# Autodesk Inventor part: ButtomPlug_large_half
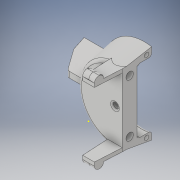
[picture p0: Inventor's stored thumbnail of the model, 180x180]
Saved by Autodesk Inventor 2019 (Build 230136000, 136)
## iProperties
Created: 2021-01
Part Number: ButtomPlug_large_half
Material: Generic
Document SubType Name: Modeling
Designer: Johnny Rex Kancaie
Density: 1 g/cm^3
Appearance: Default
Created: 2021-02
Part Number: ButtomPlug_3DPrint
Author: Johnny Rex Kancaie
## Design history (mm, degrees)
sketch "Sketch1"
  geometry: C1 r 28 at (0, 0); 1 further point
  constraints: 1 centre point, 1 coincident
  dimensions: "d0" = 56 diameter of C1
workplane "Work Plane1"
sketch "Sketch2"
  geometry: C1 r 24.5 at (0, 0); 1 further point
  constraints: 1 centre point, 1 coincident
  dimensions: "d2" = 49 diameter of C1
loft "Loft1" sketch "Sketch2" dims "d3" = 0, "d4" = 90 deg, "d5" = 0, "d6" = 90 deg
workplane "Work Plane2"
workplane "Work Plane3"
sketch "Sketch3"
  geometry: L1 (28, 0)-(-28, 0) reference; L2 (-24.5, 20)-(24.5, 20) reference; L3 (-5, 11)-(5, 11); L4 (5, 29)-(-5, 11); L5 (-5, 29)-(5, 11); L6 (-24.5, 20)-(24.5, 20) reference; L7 (5, 20)-(-5, 20); L8 (-4, 38)-(4, 38); L9 (0, 38)-(-4, 38); L10 (-4, 38)-(-5, 20); L11 (0, 38)-(4, 38); L12 (4, 38)-(5, 20); 2 further points
  constraints: 18 end point, 4 midpoint, 1 horizontal, 1 parallel, 1 point on line
  dimensions: "d9" = 10 distance of L3.end L3.start; "d13" = 4 distance of L8.start L9.start
extrude "Extrusion1" join sketch "Sketch3" distance "d15" = 2.5; taper "d16" = 0 deg
sketch "Sketch4"
  geometry: L1 (0, 0.516)-(0, 0) reference; L2 (5, 0)-(0, 0) reference; L3 (10, 0)-(5, 0) reference; L4 (10, 0.516)-(10, 0) reference; L5 (0, 0)-(0, 0.516); L6 (5, 0)-(0, 0) reference; L7 (0, 0)-(5, 0); L8 (0, 2.5)-(0, 0.516) reference; A1 r 24.5 centre (5, 24.5) between (0, 0.516) and (5, 0) reference; A2 r 24.5 centre (5, 24.5) between (5, 0) and (10, 0.516) reference; A3 r 24.5 centre (5, 24.5) between (5, 0) and (10, 0.516) reference; A4 r 24.5 centre (5, 24.5) between (0, 0.516) and (5, 0) reference; A5 r 24.5 centre (5, 24.5) between (0, 0.516) and (5, 0); 1 further point
  constraints: 4 end point, 2 point on circle, 1 centre point, 1 collinear, 1 tangent
extrude "Extrusion2" join sketch "Sketch4" distance "d17" = 4; taper "d18" = 0 deg
sketch "Sketch5"
  geometry: L1 (5, 0)-(0, 0) reference; L2 (5, 0.516)-(5, 0) reference; L3 (5, 0.516)-(5, 0) reference; L4 (5, 0.516)-(5, 0); L5 (5, 0)-(0, 0); A1 r 24.5 centre (0, 24.5) between (0, 0) and (5, 0.516) reference; A2 r 24.5 centre (0, 24.5) between (5, 0.516) and (-5, 0.516) reference; A3 r 24.5 centre (0, 24.5) between (0, 0) and (5, 0.516) reference; A4 r 24.5 centre (0, 24.5) between (0, 0) and (5, 0.516); 1 further point
  constraints: 4 end point, 2 point on circle, 1 centre point, 1 collinear, 1 concentric
extrude "Extrusion3" join sketch "Sketch5" distance "d19" = 4; taper "d20" = 0 deg
sketch "Sketch6"
  geometry: L1 (5, 20)-(5, 11); L2 (5, 11)-(-5, 11); L3 (-5, 11)-(-5, 20); L4 (-5, 29)-(5, 11); L5 (5, 29)-(-5, 11); L6 (4, 38)-(-4, 38); L7 (0, 38)-(-4, 38); L8 (-4, 38)-(-5, 20); L9 (0, 38)-(4, 38); L10 (4, 38)-(5, 20); 3 further points
  constraints: 20 end point, 3 midpoint, 1 parallel, 1 point on line
  dimensions: "d21" = 10 distance of L1.end L2.end; "d24" = 4 distance of L6.end L7.start; "d25" = 4 distance of L6.start L7.start
extrude "Extrusion4" join sketch "Sketch6" distance "d26" = 2.5; taper "d27" = 0 deg
sketch "Sketch7"
  geometry: L1 (-18.028, 0)-(0, 0) reference; L2 (0, 0)-(0, 2.5) reference; L3 (-18.028, 2.5)-(0, 2.5) reference; L4 (-18.028, 1.984)-(-18.028, 2.5) reference; L5 (-18.028, 0)-(-18.028, 1.984) reference; L6 (0, 2.5)-(0.444, 2.5) reference; L7 (-18.028, 2.5)-(0, 2.5) reference; A1 r 3 centre (-3, 2.5) between (0, 2.5) and (-6, 2.5); 1 further point
  constraints: 2 point on circle, 1 centre point, 1 point on line
  dimensions: "d28" = 6 distance of L2.end A1.end; "d29" = 3 radius of A1
  node "Projected Loop5"
sketch "Sketch8"
  geometry: L1 (0, 0)-(18.028, 0) reference; L2 (18.028, 1.984)-(18.028, 0) reference; L3 (18.028, 1.984)-(18.028, 2.5) reference; L4 (0, 2.5)-(18.028, 2.5) reference; L5 (0, 0)-(0, 2.5) reference; L6 (17.473, 2.5)-(-0.444, 2.5) reference; A1 r 3 centre (3, 2.5) between (6, 2.5) and (0, 2.5); 1 further point
  constraints: 2 point on circle, 1 centre point, 1 point on line
  dimensions: "d30" = 6 distance of L4.start A1.start; "d31" = 3 radius of A1
extrude "Extrusion5" join sketch "Sketch8" distance "d32" = 8; taper "d33" = 0 deg
extrude "Extrusion6" join sketch "Sketch7" distance "d34" = 8; taper "d35" = 0 deg
sketch "Sketch9"
  geometry: L1 (-18.028, 2.5)-(0, 2.5) reference; L2 (-18.028, 0.516)-(-18.028, 2.5) reference; L3 (-18.028, 0.516)-(-18.028, 0) reference; L4 (0, 0)-(-18.028, 0) reference; L5 (0, 2.5)-(0, 0) reference; L6 (0, 0)-(-18.028, 0) reference; A1 r 3 centre (-3, 0) between (-6, 0) and (0, 0); 1 further point
  constraints: 2 point on circle, 1 centre point, 1 point on line
  dimensions: "d36" = 6 distance of L4.start A1.start; "d37" = 3 radius of A1
extrude "Extrusion7" join sketch "Sketch9" distance "d38" = 8; taper "d39" = 0 deg
sketch "Sketch10"
  geometry: L1 (0, 2.5)-(18.028, 2.5) reference; L2 (0, 2.5)-(0, 0) reference; L3 (18.028, 0)-(0, 0) reference; L4 (18.028, 0.516)-(18.028, 0) reference; L5 (18.028, 2.5)-(18.028, 0.516) reference; L6 (18.028, 0)-(0, 0) reference; A1 r 3 centre (3, 0) between (0, 0) and (6, 0); 1 further point
  constraints: 2 point on circle, 1 centre point, 1 point on line
  dimensions: "d40" = 6 distance of L2.end A1.end; "d41" = 3 radius of A1
extrude "Extrusion8" join sketch "Sketch10" distance "d42" = 8; taper "d43" = 0 deg
sketch "Sketch11"
  geometry: 1 further point
workplane "Work Plane4"
sketch "Sketch12"
  geometry: L1 (23.984, 20)-(-23.984, 20) reference; L2 (-24.5, 17.114)-(-24.5, 20) reference; L3 (-24.5, 20)-(-24.5, 17.114) reference; L4 (-23.984, 20)-(23.984, 20) reference; L5 (24.5, 17.114)-(24.5, 20) reference; L6 (24.5, 20)-(24.5, 17.114) reference; L7 (28, 0)-(-28, 0) reference; L8 (0, 0)-(0, 17); L9 (0, 0)-(10, 0); L10 (28, 0)-(-28, 0) reference; L11 (0, 17)-(2, 17); L12 (2, 17)-(10, 0); L13 (0, 17)-(-2, 17); L14 (0, 0)-(-10, 0); L15 (-10, 0)-(-2, 17)
  constraints: 14 end point, 3 point on line, 1 parallel, 1 vertical, 4 other
  dimensions: "d47" = 17 distance of L8.start L8.end; "d48" = 10 distance of L8.start L9.end; "d49" = 2 distance of L8.end L11.end; "d50" = 2 distance of L8.end L13.end; "d51" = 10 distance of L8.start L14.end
  node "Projected Loop9"
extrude "Extrusion9" join sketch "Sketch12" distance "d52" = 17; taper "d53" = 0 deg
workplane "Work Plane5"
sketch "Sketch13"
  geometry: L1 (10, 0)-(2, 17) reference; L2 (10, 0)-(2, 17); L3 (2, 17)-(-2, 17) reference; L4 (2, 17)-(-2, 17); L5 (-2, 17)-(-10, 0) reference; L6 (-2, 17)-(-10, 0); L7 (-10, 0)-(10, 0); L8 (28, 0)-(-28, 0) reference; 1 further point
  constraints: 8 end point, 4 collinear
extrude "Extrusion10" join sketch "Sketch13" distance "d55" = 17; taper "d56" = 0 deg
chamfer "Chamfer1" distance "d57" = 10; stored, may be unused: second distance "d58" = 2, angle "d59" = 30 deg
chamfer "Chamfer2" distance "d60" = 10; stored, may be unused: second distance "d61" = 2, angle "d62" = 30 deg
fillet "Fillet3" dims "d63" = 2
sketch "Sketch14"
  geometry: C1 r 21.5 at (41, -10); 1 further point
  constraints: 1 centre point, 1 coincident
  dimensions: "d64" = 43 diameter of C1
extrude "Extrusion11" cut sketch "Sketch14" distance "d65" = 10; taper "d66" = 0 deg
sketch "Sketch15"
  geometry: L1 (14.847, 0)-(0, 0) reference; L2 (0, -20)-(0, 0) reference; L3 (14.847, -20)-(0, -20) reference; L4 (67.153, -20)-(82, -20) reference; L5 (82, 0)-(82, -20) reference; L6 (67.153, 0)-(82, 0) reference; L7 (14.847, 0)-(0, 0) reference; L8 (0, -20)-(0, 0) reference; L9 (14.847, -20)-(0, -20) reference; L10 (2.969, -16)-(10.969, -16); L11 (10.969, -16)-(10.969, -4); L12 (10.969, -4)-(2.969, -4); L13 (2.969, -4)-(2.969, -16); L14 (2.969, -16)-(10.969, -4); L15 (10.969, -16)-(2.969, -4); L16 (67.153, 0)-(82, 0) reference; L17 (82, 0)-(82, -20) reference; L18 (71.072, -16)-(79.072, -16); L19 (79.072, -16)-(79.072, -4); L20 (79.072, -4)-(71.072, -4); L21 (71.072, -4)-(71.072, -16); L22 (75.072, -12)-(75.072, -8) reference; L23 (71.072, -16)-(79.072, -4); L24 (79.072, -16)-(71.072, -4); C1 r 21.5 at (41, -10) reference; A1 r 28 centre (41, -10) between (67.153, 0) and (14.847, 0) reference; A2 r 28 centre (41, -10) between (14.847, -20) and (67.153, -20) reference; 3 further points
  constraints: 24 end point, 5 midpoint, 4 parallel, 2 horizontal, 2 perpendicular
  dimensions: "d67" = 12 distance of L12.end L10.start; "d68" = 12 distance of L18.end L19.end; "d69" = 8 distance of L19.end L20.end; "d70" = 8 distance of L11.end L12.end
extrude "Extrusion12" cut sketch "Sketch15" distance "d71" = 6; taper "d72" = 0 deg
sketch "Sketch18"
  geometry: C1 r 21.5 at (0, 0) reference; C2 r 2 at (0, 0); 1 further point
  constraints: 1 centre point, 1 coincident
  dimensions: "d77" = 4 diameter of C2
extrude "Extrusion15" cut sketch "Sketch18" extent not by distance; stored distance "d78" = 2; taper "d79" = 0 deg
fillet "Fillet5" dims "d81" = 2
sketch "Sketch20"
  geometry: C1 r 22.5 at (41, -10); 1 further point
  constraints: 1 centre point, 1 coincident
  dimensions: "d82" = 45 diameter of C1
extrude "Extrusion16" cut sketch "Sketch20" distance "d83" = 8; taper "d84" = 0 deg
fillet "Fillet6" dims "d85" = 5
fillet "Fillet7" dims "d86" = 2
workplane "Work Plane6"
sketch "Sketch21"
  geometry: L1 (28, 0)-(24.5, 20) reference; L2 (28, 0)-(24.5, 20); L3 (24.5, 32.009)-(24.5, 20) reference; L4 (-24.5, 20)-(-22.265, 20) reference; L5 (24.5, 20)-(-24.5, 20); L6 (-24.5, 20)-(-28, 0); L7 (-28, 0)-(-24.5, 20) reference; L8 (28, 0)-(10, 0) reference; L9 (-28, 0)-(28, 0); 1 further point
  constraints: 8 end point, 3 point on line, 1 collinear, 1 horizontal
extrude "Extrusion17" cut sketch "Sketch21" distance "d88" = 41.25; taper "d89" = 0 deg
sketch "Sketch22"
  geometry: L1 (2.471, 16)-(-2.471, 16) reference; L2 (20.911, 10)-(-20.911, 10) reference; L3 (-22, 20)-(22, 20) reference; 4 further points
  dimensions: "d90" = 5 distance from line of point (-18.036, 15) L2; "d91" = 5 distance from line of L2 point (17.964, 15); "d92" = 5 distance from line of L3 point (-0.036, 15); "d93" = 18 distance of point (-0.036, 15) point (-18.036, 15); "d94" = 18 distance of point (17.964, 15) point (-0.036, 15)
sketch "Sketch23"
  geometry: L1 (-21.937, 0)-(-27.55, 0) reference; L2 (-21.937, 8)-(-21.937, 0) reference; L3 (21.937, 0)-(21.937, 8) reference; L4 (27.55, 0)-(21.937, 0) reference; 3 further points
  dimensions: "d95" = 3.5 distance from line of point (-24.437, 3.5) L1; "d96" = 2.5 distance from line of L2 point (-24.437, 3.5); "d97" = 2.5 distance from line of L3 point (24.437, 3.5); "d98" = 3.5 distance from line of L4 point (24.437, 3.5)
hole "Hole1" sketch "Sketch22" diameter "d99" = 5; stored, may be unused: countersink angle "d103" = 90 deg, drill point angle "d105" = 0 deg; dims "d100" = 6, "d101" = 4, "d102" = 2, "d104" = 10
hole "Hole2" sketch "Sketch23" diameter "d106" = 3; stored, may be unused: countersink angle "d110" = 90 deg, drill point angle "d112" = 0 deg; dims "d107" = 6, "d108" = 4, "d109" = 2, "d111" = 10
fillet "Fillet8" dims "d113" = 2
fillet "Fillet9" dims "d114" = 1
body "Solid1"
node "Projected Loop1"
node "Projected Loop2"
node "Projected Loop3"
node "Projected Loop4"
node "Projected Loop6"
node "Projected Loop7"
node "Projected Loop8"
node "Projected Loop10"
node "Projected Loop13"
other parameters: "d7" = 22, "d8" = -22, "d46" = 24, "d54" = -24, "d87" = 5
